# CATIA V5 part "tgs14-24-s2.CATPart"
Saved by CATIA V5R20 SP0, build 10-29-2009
Part number: TGS14-24-S2
Definition: design
Nomenclature: TGS14-24-S2
Source: made
Description: NOT SPECIFIED
Bounding box of the stored display mesh (mm): x -22 to 0.8, y 0 to 14, z -6 to 6
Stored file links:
  C:\Users\Raffaele\Desktop\3D X SITO CF\I-MOLD\TGS-S2\tgs14-s2.step\tgs14-24-s2.CATPart
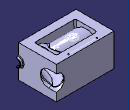
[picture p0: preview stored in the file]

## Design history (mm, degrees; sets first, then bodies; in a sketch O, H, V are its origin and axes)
Set1
  Line1 "LINE #4147": stored without definition
  DatumCurve1 "COMPOSITE_CURVE #4200"
  DatumCurve2 "COMPOSITE_CURVE #4251"
  DatumCurve3 "COMPOSITE_CURVE #4330"
  DatumCurve4 "COMPOSITE_CURVE #4373"
  DatumCurve5 "COMPOSITE_CURVE #4602"
  DatumCurve6 "COMPOSITE_CURVE #4743"
  DatumCurve7 "COMPOSITE_CURVE #4770"
  DatumCurve8 "COMPOSITE_CURVE #4828"
  DatumCurve9 "COMPOSITE_CURVE #4883"
  DatumCurve10 "COMPOSITE_CURVE #4912"
  DatumSurface1 "OPEN_SHELL #4137"
Body1 "MANIFOLD_SOLID_BREP #4138" (main body)
  Solid1: solid without history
